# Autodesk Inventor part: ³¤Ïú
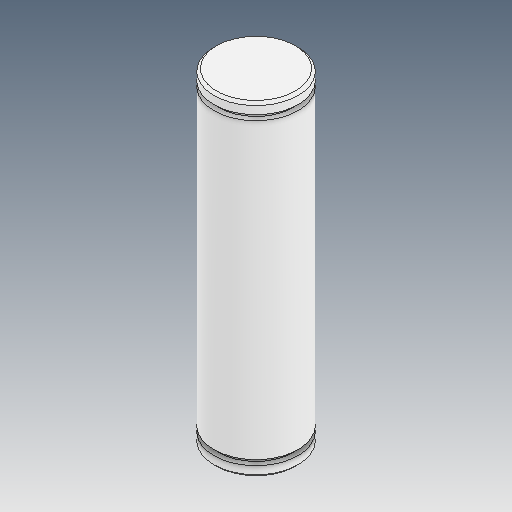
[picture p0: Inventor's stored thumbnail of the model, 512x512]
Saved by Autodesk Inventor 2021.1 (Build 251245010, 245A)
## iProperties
Created: 2021-05
Part Number: ³¤Ïú
Material: Ogólny
Document SubType Name: Modeling
Designer: user
Density: 1 g/cm^3
Appearance: Domyślna
Author: user
Revision Number: ÈÎºÎ
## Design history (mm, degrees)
feature "ÊäÈë1"
node "Bryła1"
